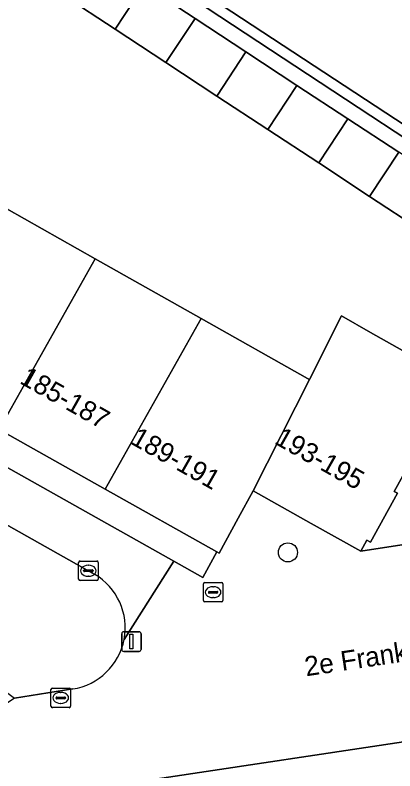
# Model space of a CAD drawing. Extents: x 159279 to 160377, y 384531 to 385888.
# Drawn here: x 159709.16 to 159728.58, y 384897.02 to 384935.7 of the extents above; entities that cross this region are included whole.
import ezdxf

# ---------------------------------------------------------------- set-up
doc = ezdxf.new("R2010")
doc.units = 0
for name, color, linetype in [('IMGEO_Boom', 7, 'Continuous'), ('IMGEO_Brandkraan', 7, 'Continuous'), ('IMGEO_Erf', 7, 'Continuous'), ('IMGEO_Groenvoorziening', 7, 'Continuous'), ('IMGEO_Lichtmast', 7, 'Continuous'), ('IMGEO_Openbare_ruimte_label', 7, 'Continuous'), ('IMGEO_Pand', 7, 'Continuous'), ('IMGEO_Pand_nummerreeks', 7, 'Continuous'), ('IMGEO_Parkeervlak_open', 7, 'Continuous'), ('IMGEO_Rioolput', 7, 'Continuous'), ('IMGEO_Voetpad_open', 7, 'Continuous')]:
    doc.layers.add(name, color=color, linetype=linetype)

msp = doc.modelspace()

# ---------------------------------------------------------------- linework, layer by layer
at = {"layer": 'IMGEO_Boom'}
msp.add_circle((159723.11, 384908.2), 0.489, dxfattribs=at)
at = {"layer": 'IMGEO_Brandkraan'}
for p, q in [((159718.861, 384906.663), (159719.713, 384906.663)), ((159718.786, 384905.737), (159718.786, 384906.589)), ((159719.274, 384906.443), (159719.299, 384906.443)), ((159719.787, 384906.589), (159719.787, 384905.737)), ((159719.045, 384906.157), (159719.045, 384906.169)), ((159719.483, 384906.12), (159719.085, 384906.12)), ((159719.088, 384906.206), (159719.486, 384906.206)), ((159719.297, 384905.883), (159719.272, 384905.883)), ((159719.529, 384906.169), (159719.529, 384906.157)), ((159719.713, 384905.663), (159718.861, 384905.663))]:
    msp.add_line(p, q, dxfattribs=at)
for points in [[(159718.861, 384906.663), (159719.713, 384906.663)], [(159718.786, 384905.737), (159718.786, 384906.589)], [(159719.787, 384906.589), (159719.787, 384905.737)], [(159719.713, 384905.663), (159718.861, 384905.663)]]:
    msp.add_lwpolyline(points, dxfattribs=at)
for centre, radius, start, end in [((159718.863, 384906.587), 0.0765, 91.552, 178.448), ((159718.863, 384906.587), 0.0765, 91.552, 178.448), ((159719.711, 384906.587), 0.0765, 1.552, 88.448), ((159719.711, 384906.587), 0.0765, 1.552, 88.448), ((159719.085, 384906.166), 0.0403, 85.8775, 175.7526), ((159719.082, 384906.156), 0.0366, 178.938, 274.7102), ((159719.486, 384906.163), 0.043, 264.8664, 352.4533), ((159719.49, 384906.168), 0.0386, 1.7309, 96.639), ((159718.863, 384905.739), 0.0765, 181.552, 268.448), ((159718.863, 384905.739), 0.0765, 181.552, 268.448), ((159719.711, 384905.739), 0.0765, 271.552, 358.448), ((159719.711, 384905.739), 0.0765, 271.552, 358.448)]:
    msp.add_arc(centre, radius, start, end, dxfattribs=at)
for centre, major_axis, ratio, start_param, end_param in [((159719.273, 384906.163), (-0.387, 0.002), 0.722429, 4.712389, 7.853982), ((159719.298, 384906.163), (-0.39, 0.002), 0.717154, 1.570796, 4.712389)]:
    msp.add_ellipse(centre, major_axis=major_axis, ratio=ratio, start_param=start_param, end_param=end_param, dxfattribs=at)
at = {"layer": 'IMGEO_Erf'}
for points in [[(159732.03, 384914.588), (159734.623, 384916.992), (159732.923, 384918.784), (159737.5, 384923.127), (159739.201, 384921.335), (159739.825, 384922.747), (159739.415, 384923.231), (159735.306, 384925.93), (159735.022, 384925.5), (159706.801, 384944.073), (159706.591, 384943.78), (159674.116, 384964.946)], [(159643.607, 384964.181), (159647.503, 384959.44), (159651.4, 384954.699), (159649.084, 384952.791), (159652.211, 384950.895), (159656.129, 384948.52), (159658.903, 384953.838), (159664.337, 384950.777), (159669.772, 384947.716), (159675.206, 384944.655), (159680.641, 384941.594), (159686.075, 384938.533), (159691.51, 384935.472), (159696.944, 384932.411), (159702.378, 384929.35), (159707.813, 384926.289), (159713.247, 384923.228), (159718.682, 384920.167), (159724.116, 384917.106), (159724.215, 384917.05), (159725.856, 384920.3), (159727.342, 384919.461), (159731.696, 384917.004), (159730.233, 384914.369)], [(159679.301, 384961.226), (159681.905, 384959.513), (159684.509, 384957.799), (159687.113, 384956.086), (159689.717, 384954.373), (159692.321, 384952.66), (159694.925, 384950.946), (159697.529, 384949.233), (159700.132, 384947.52), (159702.736, 384945.807), (159705.34, 384944.094), (159707.944, 384942.38), (159710.548, 384940.667), (159713.152, 384938.954), (159715.756, 384937.241), (159718.36, 384935.527), (159720.964, 384933.814), (159723.568, 384932.101), (159726.172, 384930.388), (159728.776, 384928.675)], [(159729.894, 384924.703), (159727.29, 384926.416), (159724.686, 384928.129), (159722.082, 384929.842), (159719.478, 384931.555), (159716.874, 384933.269), (159714.27, 384934.982), (159711.666, 384936.695), (159709.062, 384938.408), (159706.458, 384940.122), (159703.854, 384941.835), (159701.25, 384943.548), (159698.646, 384945.261), (159696.042, 384946.974), (159693.438, 384948.688), (159690.834, 384950.401), (159688.231, 384952.114), (159685.627, 384953.827), (159683.023, 384955.541), (159680.419, 384957.254), (159677.815, 384958.967), (159675.211, 384960.68)]]:
    msp.add_lwpolyline(points, dxfattribs=at)
at = {"layer": 'IMGEO_Groenvoorziening'}
msp.add_lwpolyline([(159707.106, 384944.499), (159706.801, 384944.073), (159735.022, 384925.5), (159735.306, 384925.93), (159729.157, 384930.006)], close=True, dxfattribs=at)
for points in [[(159713.23, 384907.077), (159694.777, 384917.475)], [(159699.55, 384907.887), (159709.133, 384900.743), (159712.108, 384901.21)]]:
    msp.add_lwpolyline(points, dxfattribs=at)
for centre, radius, start, end in [((159711.618, 384904.346), 3.171, 349.1404, 59.441), ((159711.617, 384904.343), 3.172, 278.9133, 349.2004)]:
    msp.add_arc(centre, radius, start, end, dxfattribs=at)
at = {"layer": 'IMGEO_Lichtmast'}
for p, q in [((159714.612, 384903.236), (159714.612, 384904.036)), ((159714.612, 384904.036), (159714.612, 384903.236)), ((159714.712, 384904.136), (159715.502, 384904.136)), ((159715.502, 384904.136), (159714.712, 384904.136)), ((159715.602, 384904.036), (159715.602, 384903.236)), ((159715.602, 384903.236), (159715.602, 384904.036)), ((159715.502, 384903.136), (159714.712, 384903.136)), ((159714.712, 384903.136), (159715.502, 384903.136))]:
    msp.add_line(p, q, dxfattribs=at)
msp.add_lwpolyline([(159715.032, 384904.011), (159715.182, 384904.011), (159715.182, 384903.261), (159715.032, 384903.261), (159715.032, 384904.011)], dxfattribs=at)
for centre, start, end in [((159714.712, 384904.036), 90, 180), ((159714.712, 384904.036), 90, 180), ((159715.502, 384904.036), 0, 90), ((159715.502, 384904.036), 360, 90), ((159714.712, 384903.236), 180, 270), ((159714.712, 384903.236), 180, 270), ((159715.502, 384903.236), 270, 0), ((159715.502, 384903.236), 270, 0)]:
    msp.add_arc(centre, 0.1, start, end, dxfattribs=at)
at = {"layer": 'IMGEO_Pand'}
for points in [[(159715.756, 384937.241), (159713.152, 384938.954), (159711.666, 384936.695), (159714.27, 384934.982)], [(159718.36, 384935.527), (159715.756, 384937.241), (159714.27, 384934.982), (159716.874, 384933.269)], [(159716.874, 384933.269), (159719.478, 384931.555), (159720.964, 384933.814), (159718.36, 384935.527)], [(159719.478, 384931.555), (159722.082, 384929.842), (159723.568, 384932.101), (159720.964, 384933.814)], [(159726.172, 384930.388), (159723.568, 384932.101), (159722.082, 384929.842), (159724.686, 384928.129)], [(159724.686, 384928.129), (159727.29, 384926.416), (159728.776, 384928.675), (159726.172, 384930.388)], [(159727.29, 384926.416), (159729.894, 384924.703), (159731.38, 384926.961), (159728.776, 384928.675)], [(159708.322, 384914.484), (159713.247, 384923.228), (159707.813, 384926.289), (159702.884, 384917.538)], [(159713.76, 384911.429), (159718.682, 384920.167), (159713.247, 384923.228), (159708.322, 384914.484)], [(159724.215, 384917.05), (159724.116, 384917.106), (159718.682, 384920.167), (159713.76, 384911.429), (159719.473, 384908.221), (159719.587, 384908.157), (159720.573, 384909.957), (159721.334, 384911.346)], [(159730.233, 384914.369), (159731.696, 384917.004), (159727.342, 384919.461), (159725.856, 384920.3), (159724.215, 384917.05), (159721.334, 384911.346), (159724.304, 384909.683), (159726.842, 384908.261), (159727.153, 384908.821), (159727.328, 384908.724), (159728.717, 384911.225), (159728.542, 384911.323)]]:
    msp.add_lwpolyline(points, close=True, dxfattribs=at)
at = {"layer": 'IMGEO_Parkeervlak_open'}
msp.add_lwpolyline([(159709.871, 384948.728), (159707.106, 384944.499), (159729.157, 384930.006), (159735.306, 384925.93), (159739.415, 384923.231), (159742.182, 384927.456)], close=True, dxfattribs=at)
msp.add_lwpolyline([(159736.842, 384899.677), (159709.185, 384895.515)], dxfattribs=at)
at = {"layer": 'IMGEO_Rioolput'}
for p, q in [((159712.405, 384906.833), (159712.405, 384907.685)), ((159712.48, 384907.759), (159713.332, 384907.759)), ((159712.893, 384907.539), (159712.918, 384907.539)), ((159713.406, 384907.685), (159713.406, 384906.833)), ((159712.664, 384907.253), (159712.664, 384907.265)), ((159713.102, 384907.216), (159712.704, 384907.216)), ((159712.707, 384907.302), (159713.105, 384907.302)), ((159713.148, 384907.265), (159713.148, 384907.253)), ((159713.332, 384906.759), (159712.48, 384906.759)), ((159712.916, 384906.979), (159712.891, 384906.979)), ((159711.067, 384901.254), (159711.919, 384901.254)), ((159710.992, 384900.328), (159710.992, 384901.18)), ((159711.48, 384901.034), (159711.505, 384901.034)), ((159711.993, 384901.18), (159711.993, 384900.328)), ((159711.251, 384900.748), (159711.251, 384900.76)), ((159711.689, 384900.711), (159711.291, 384900.711)), ((159711.294, 384900.797), (159711.692, 384900.797)), ((159711.503, 384900.474), (159711.478, 384900.474)), ((159711.735, 384900.76), (159711.735, 384900.748)), ((159711.919, 384900.254), (159711.067, 384900.254))]:
    msp.add_line(p, q, dxfattribs=at)
for points in [[(159712.405, 384906.833), (159712.405, 384907.685)], [(159712.48, 384907.759), (159713.332, 384907.759)], [(159713.406, 384907.685), (159713.406, 384906.833)], [(159713.332, 384906.759), (159712.48, 384906.759)], [(159711.067, 384901.254), (159711.919, 384901.254)], [(159710.992, 384900.328), (159710.992, 384901.18)], [(159711.993, 384901.18), (159711.993, 384900.328)], [(159711.919, 384900.254), (159711.067, 384900.254)]]:
    msp.add_lwpolyline(points, dxfattribs=at)
for centre, radius, start, end in [((159712.482, 384907.683), 0.0765, 91.552, 178.448), ((159712.482, 384907.683), 0.0765, 91.552, 178.448), ((159713.33, 384907.683), 0.0765, 1.552, 88.448), ((159713.33, 384907.683), 0.0765, 1.552, 88.448), ((159712.704, 384907.262), 0.0403, 85.8775, 175.7526), ((159712.701, 384907.252), 0.0366, 178.938, 274.7102), ((159713.105, 384907.259), 0.043, 264.8664, 352.4533), ((159713.109, 384907.264), 0.0386, 1.7309, 96.639), ((159712.482, 384906.835), 0.0765, 181.552, 268.448), ((159712.482, 384906.835), 0.0765, 181.552, 268.448), ((159713.33, 384906.835), 0.0765, 271.552, 358.448), ((159713.33, 384906.835), 0.0765, 271.552, 358.448), ((159711.069, 384901.178), 0.0765, 91.552, 178.448), ((159711.069, 384901.178), 0.0765, 91.552, 178.448), ((159711.917, 384901.178), 0.0765, 1.552, 88.448), ((159711.917, 384901.178), 0.0765, 1.552, 88.448), ((159711.291, 384900.757), 0.0403, 85.8775, 175.7526), ((159711.288, 384900.747), 0.0366, 178.938, 274.7102), ((159711.692, 384900.754), 0.043, 264.8664, 352.4533), ((159711.696, 384900.759), 0.0386, 1.7309, 96.639), ((159711.069, 384900.33), 0.0765, 181.552, 268.448), ((159711.069, 384900.33), 0.0765, 181.552, 268.448), ((159711.917, 384900.33), 0.0765, 271.552, 358.448), ((159711.917, 384900.33), 0.0765, 271.552, 358.448)]:
    msp.add_arc(centre, radius, start, end, dxfattribs=at)
for centre, major_axis, ratio, start_param, end_param in [((159712.892, 384907.259), (-0.387, 0.002), 0.722429, 4.712389, 7.853982), ((159712.917, 384907.259), (-0.39, 0.002), 0.717154, 1.570796, 4.712389), ((159711.479, 384900.754), (-0.387, 0.002), 0.722429, 4.712389, 7.853982), ((159711.504, 384900.754), (-0.39, 0.002), 0.717154, 1.570796, 4.712389)]:
    msp.add_ellipse(centre, major_axis=major_axis, ratio=ratio, start_param=start_param, end_param=end_param, dxfattribs=at)
at = {"layer": 'IMGEO_Voetpad_open'}
msp.add_lwpolyline([(159686.569, 384926.7), (159681.131, 384929.755), (159675.692, 384932.809), (159670.254, 384935.863), (159664.816, 384938.917), (159659.377, 384941.971), (159654.078, 384944.948), (159653.389, 384943.716), (159717.281, 384907.744), (159718.765, 384906.908), (159719.473, 384908.221), (159713.76, 384911.429), (159708.322, 384914.484), (159702.884, 384917.538), (159697.445, 384920.592), (159692.007, 384923.646)], close=True, dxfattribs=at)
for points in [[(159714.732, 384903.749), (159717.281, 384907.744), (159653.389, 384943.716)], [(159693.808, 384915.776), (159694.362, 384916.747), (159694.777, 384917.475), (159713.23, 384907.077)], [(159730.233, 384914.369), (159728.542, 384911.323), (159728.717, 384911.225), (159727.328, 384908.724), (159727.153, 384908.821), (159726.842, 384908.261), (159730.485, 384908.825)], [(159756.564, 384912.825), (159756.548, 384912.717), (159748.702, 384911.539), (159745.566, 384911.069), (159745.373, 384911.048), (159744.521, 384910.928), (159737.079, 384909.822), (159735.507, 384909.592), (159730.485, 384908.825), (159726.842, 384908.261), (159724.304, 384909.683), (159721.334, 384911.346), (159720.573, 384909.957), (159719.587, 384908.157), (159719.473, 384908.221), (159718.765, 384906.908), (159717.281, 384907.744), (159714.732, 384903.749)], [(159712.108, 384901.21), (159709.133, 384900.743), (159708.256, 384900.166), (159707.111, 384899.413), (159705.613, 384897.977), (159703.964, 384896.367), (159697.208, 384889.759)], [(159709.185, 384895.515), (159736.842, 384899.677)]]:
    msp.add_lwpolyline(points, dxfattribs=at)
for centre, radius, start, end in [((159711.618, 384904.346), 3.171, 349.1404, 59.441), ((159711.617, 384904.343), 3.172, 278.9133, 349.2004)]:
    msp.add_arc(centre, radius, start, end, dxfattribs=at)

# ---------------------------------------------------------------- texts
at = {"layer": 'IMGEO_Openbare_ruimte_label'}
msp.add_text('2e Franklinstraat', height=1, rotation=8.5676, dxfattribs=at).set_placement((159724.047, 384901.857))
at = {"layer": 'IMGEO_Pand_nummerreeks'}
for s, rotation, p in [('185-187', 330.5557, (159709.343, 384916.88)), ('189-191', 330.3953, (159715.004, 384913.793)), ('193-195', 330.401, (159722.367, 384913.793))]:
    msp.add_text(s, height=1, rotation=rotation, dxfattribs=at).set_placement(p)

doc.saveas('drawing.dxf')
